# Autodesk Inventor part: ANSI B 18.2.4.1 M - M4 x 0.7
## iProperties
Comments: To add or edit properties for Autodesk Inventor files, use iProperties.
Created: 2004-08
Part Number: ANSI B 18.2.4.1 M - M4 x 0.7
Vendor: Autodesk Inc.
Document SubType Name: Modeling
Designer: John Blackburn
Material: Default
Description: Hex Nut
Standard: ANSI B 18.2.4.1 M
Size Designation: M4 x 0.7
Alert: To add or edit properties for Autodesk Inventor files, use iProperties.
Control State: 0
Master: False
Checked Out: False
Shininess: 64.0
Length Units: 11269
Angle Units: 11279
Time Units: 11290
Mass Units: 11283
Length Display Precision: 3
Angle Display Precision: 2
Compacted: True
EGR: 1
Classification: un/spsc 31161727
Density: 0.0
Volumn: 0.0
Area: 0.0
PropertySet Name: Model Information
Author: John Blackburn
Revision Number: 8
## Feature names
1. Body [Extrusion]
2. Chamfer1 [Revolution]
3. Thread [Hole]
4. Chamfer2
5. Chamfer3
